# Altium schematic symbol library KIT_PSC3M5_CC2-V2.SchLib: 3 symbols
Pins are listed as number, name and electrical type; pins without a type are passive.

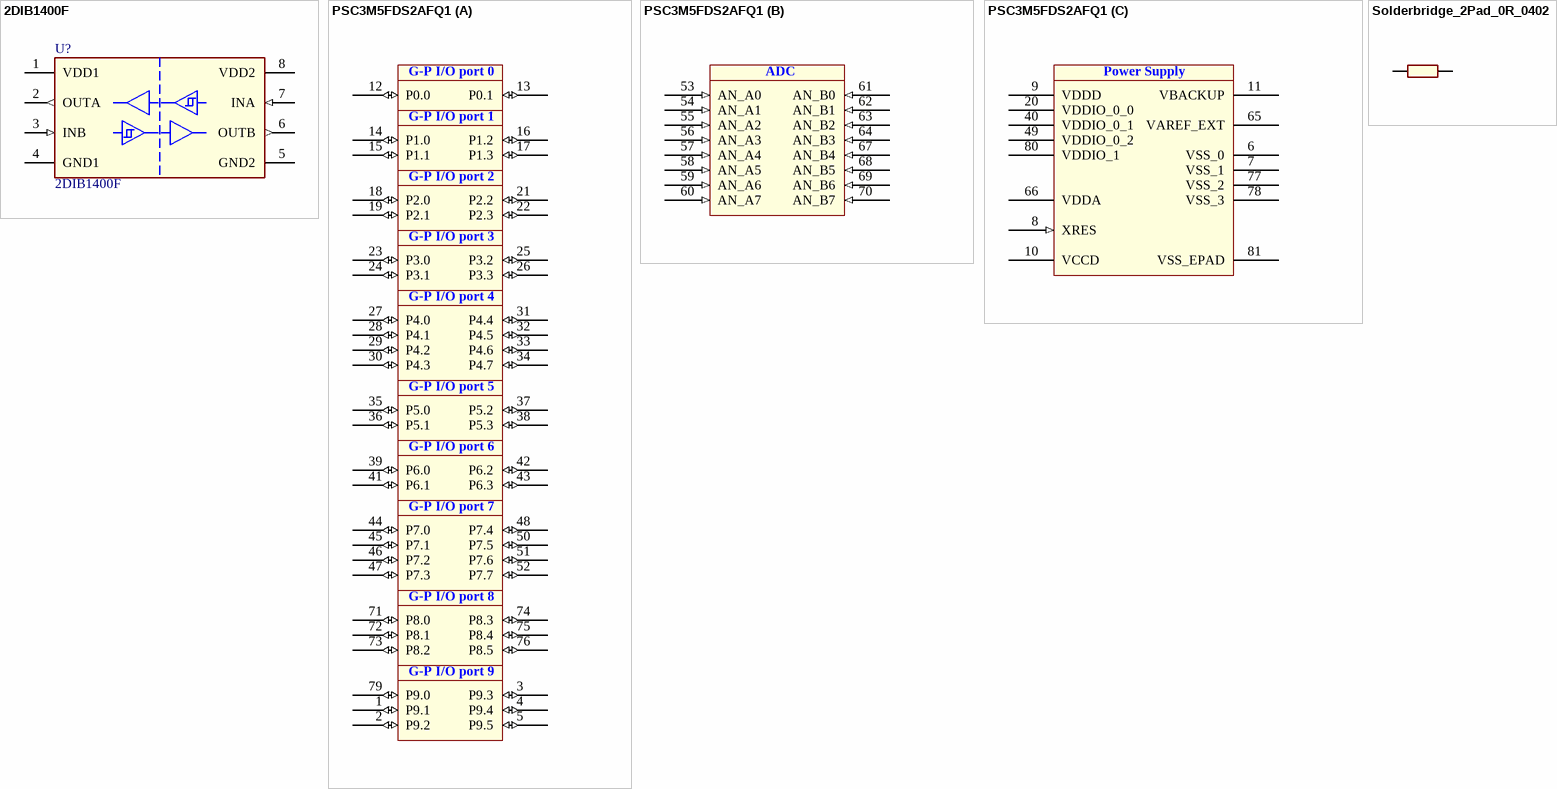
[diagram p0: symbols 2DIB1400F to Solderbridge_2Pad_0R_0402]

## 2DIB1400F
designator U?
Robust Digital Isolator, 1 Forward 1 Reverse Channel Configuration; Manufacturer: Infineon Technologies
footprint SOIC127P600X175-8N-22-V1 (SOIC,1.27mm pitch;8 pin,3.90mm W X 4.90mm L X 1.75mm H body)
pins: 1 VDD1 (power) "Positive supply voltage 1", 2 OUTA (out) "Channel A output", 3 INB (in) "Channel B Input", 4 GND1 (power) "Ground 1", 5 GND2 (power) "Ground 2", 6 OUTB (out) "Channel B Output", 7 INA (in) "Channel A Input", 8 VDD2 (power) "Positive Supply Voltage 2"

## PSC3M5FDS2AFQ1
designator U?
PSoC C3 Main Line, Cortex-M33, 180 MHz, 64KB SRAM, 256KB Flash, E-LQFP-80; Manufacturer: Infineon Technologies AG; Designer: Kr; CheckOrientation: true
footprint QFP50P1400X1400X160-81N (QFP,0.50mm pitch,square;80 pin,12.00mm L X 12.00mm W X 1.60mm H body (w/thermal tab))
part A pins: 1 P9.1 (io) "GPIO", 2 P9.2 (io) "GPIO", 3 P9.3 (io) "GPIO", 4 P9.4 (io) "GPIO", 5 P9.5 (io) "GPIO", 12 P0.0 (io) "GPIO", 13 P0.1 (io) "GPIO", 14 P1.0 (io) "GPIO", 15 P1.1 (io) "GPIO", 16 P1.2 (io) "GPIO", 17 P1.3 (io) "GPIO", 18 P2.0 (io) "GPIO", 19 P2.1 (io) "GPIO", 21 P2.2 (io) "GPIO", 22 P2.3 (io) "GPIO", 23 P3.0 (io) "GPIO", 24 P3.1 (io) "GPIO", 25 P3.2 (io) "GPIO", 26 P3.3 (io) "GPIO", 27 P4.0 (io) "GPIO", 28 P4.1 (io) "GPIO", 29 P4.2 (io) "GPIO", 30 P4.3 (io) "GPIO", 31 P4.4 (io) "GPIO", 32 P4.5 (io) "GPIO", 33 P4.6 (io) "GPIO", 34 P4.7 (io) "GPIO", 35 P5.0 (io) "GPIO", 36 P5.1 (io) "GPIO", 37 P5.2 (io) "GPIO", 38 P5.3 (io) "GPIO", 39 P6.0 (io) "GPIO", 41 P6.1 (io) "GPIO", 42 P6.2 (io) "GPIO", 43 P6.3 (io) "GPIO", 44 P7.0 (io) "GPIO", 45 P7.1 (io) "GPIO", 46 P7.2 (io) "GPIO", 47 P7.3 (io) "GPIO", 48 P7.4 (io) "GPIO", 50 P7.5 (io) "GPIO", 51 P7.6 (io) "GPIO", 52 P7.7 (io) "GPIO", 71 P8.0 (io) "GPIO", 72 P8.1 (io) "GPIO", 73 P8.2 (io) "GPIO", 74 P8.3 (io) "GPIO", 75 P8.4 (io) "GPIO", 76 P8.5 (io) "GPIO", 79 P9.0 (io) "GPIO"
part B pins: 53 AN_A0 (in) "ADC Input", 54 AN_A1 (in) "ADC Input", 55 AN_A2 (in) "ADC Input", 56 AN_A3 (in) "ADC Input", 57 AN_A4 (in) "ADC Input", 58 AN_A5 (in) "ADC Input", 59 AN_A6 (in) "ADC Input", 60 AN_A7 (in) "ADC Input", 61 AN_B0 (in) "ADC Input", 62 AN_B1 (in) "ADC Input", 63 AN_B2 (in) "ADC Input", 64 AN_B3 (in) "ADC Input", 67 AN_B4 (in) "ADC Input", 68 AN_B5 (in) "ADC Input", 69 AN_B6 (in) "ADC Input", 70 AN_B7 (in) "ADC Input"
part C pins: 6 VSS_0 (power) "GND", 7 VSS_1 (power) "GND", 8 XRES (in) "Reset", 9 VDDD (power) "Main regulated supply", 10 VCCD (power) "Main regulated supply", 11 VBACKUP (power) "Power", 20 VDDIO_0_0 (power) "Main regulated supply", 40 VDDIO_0_1 (power) "Main regulated supply", 49 VDDIO_0_2 (power) "Main regulated supply", 65 VAREF_EXT (power) "Power", 66 VDDA (power) "Main regulated supply", 77 VSS_2 (power) "GND", 78 VSS_3 (power) "GND", 80 VDDIO_1 (power) "Main regulated supply", 81 VSS_EPAD (power) "GND"

## Solderbridge_2Pad_0R_0402
designator R?, comment 0R
SMD solderbridge, 2 Pads, 0R resistor populated, 0402 size; PartNumber: 01.02.0902.0; Designer: Ma; CheckOrientation: false
simulation model RES (Resistor)
signal-integrity model R0402
footprint RESC1005N (Chip Resistor, Body 1.1x0.5mm, IPC Medium Density)
footprint RESC1005M (Chip Resistor, Body 1.1x0.5mm, IPC Low Density)
footprint RESC1005L (Chip Resistor, Body 1.1x0.5mm, IPC High Density)
footprint Chip_1005_[0402]_L (Chip Resistor, Body 1.1x0.5mm, IPC High Density)
pins: 1, 2
1 alternate drawing of the same symbol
